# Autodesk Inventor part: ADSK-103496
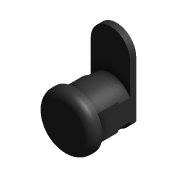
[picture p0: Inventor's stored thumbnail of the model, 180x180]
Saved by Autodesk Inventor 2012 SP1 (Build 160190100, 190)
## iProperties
Shininess: 0.0
Created: 2000-10
Part Number: ADSK-103496
Checked By: PT
Description: SPAENAUR INC.
Document SubType Name: Modeling
Designer: Gary
Stock Number: ADSK-103496
Density: 1 g/cm^3
Material: Default
Density: 0.0
Volumn: 0.0
Area: 0.0
PropertySet Name: Model Information
Control State: 0
Master: False
Checked Out: False
Title: CARBIN LOCK
Author: Gary
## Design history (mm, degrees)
node "Extrusion1" dims "d1" = 4.7625, "d2" = 0
  sketch "Sketch1"
    geometry: C1 r 11.113 at (0, 0)
    constraints: 1 centre point
    dimensions: "d0" = 22.225 diameter of C1
node "Fillet1" dims "d3" = 3.175
node "Extrusion2" dims "d5" = 9.525, "d6" = 0
  sketch "Sketch2"
    geometry: C1 r 11.112 at (0, 0) reference; C2 r 9.525 at (0, 0)
    constraints: 1 centre point, 1 coincident
    dimensions: "d4" = 19.05 diameter of C2
node "Extrusion3" dims "d7" = 4.7625, "d8" = 0
  sketch "Sketch3"
    geometry: C1 r 9.525 at (0, 0) reference; C2 r 8.997 at (0, 0)
    constraints: 1 centre point
node "Extrusion4" dims "d10" = 2.54, "d11" = 0
  sketch "Sketch4"
    geometry: C1 r 8.997 at (0, 0) reference; C2 r 25.4 at (0, 0)
    constraints: 1 centre point
    dimensions: "d9" = 50.8 diameter of C2
node "Extrusion5" dims "d14" = 16.51, "d15" = 0
  sketch "Sketch5"
    geometry: L1 (-7.938, -5.265)-(-7.938, 17.462); L2 (7.938, -5.265)-(7.938, 17.462); C1 r 25.4 at (0, 0) reference; A1 r 7.938 centre (0, 0) between (-7.938, 0) and (7.938, 0); A2 r 7.938 centre (0, 17.462) between (7.938, 17.462) and (-7.938, 17.462); A3 r 9.525 centre (0, 0) between (-7.938, -5.265) and (7.938, -5.265)
    constraints: 6 point on circle, 4 end point, 3 centre point, 3 tangent, 2 point on line, 1 coincident, 1 parallel, 1 vertical
    dimensions: "d12" = 15.875 diameter of A1; "d13" = 19.05 diameter of A3
body "Solid1"
